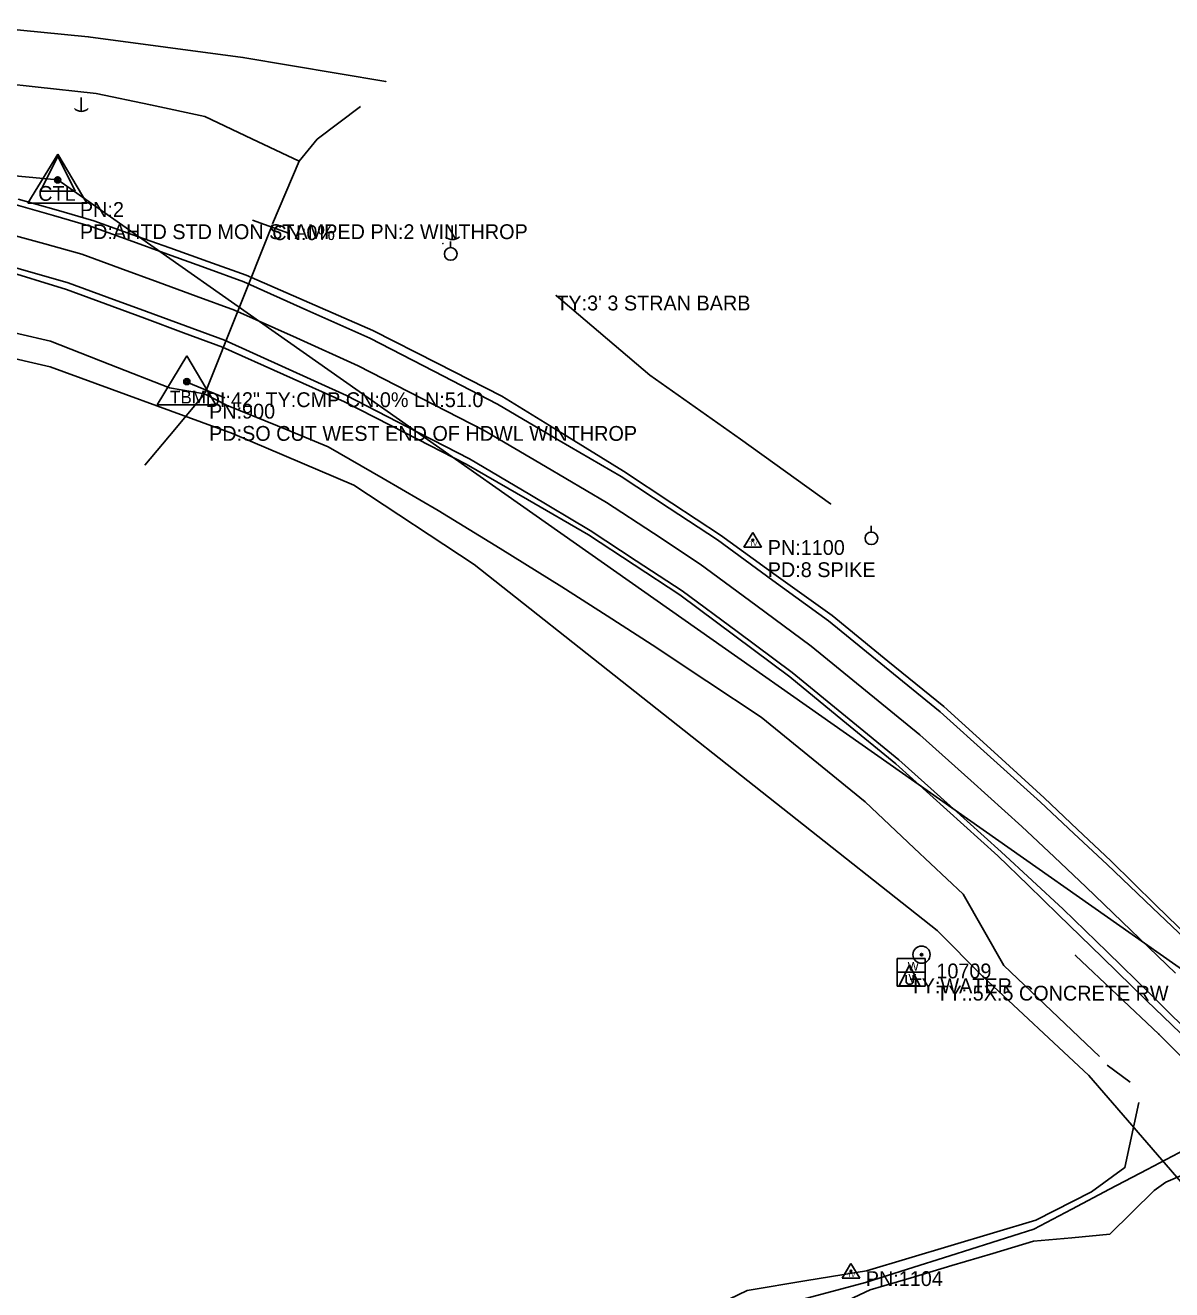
# Model space of a CAD drawing. Extents: x 592653 to 596268, y 1744647 to 1746025.
# Drawn here: x 593745.6 to 594132.6, y 1745515.6 to 1745942.5 of the extents above; entities that cross this region are included whole.
import ezdxf

# ---------------------------------------------------------------- set-up
doc = ezdxf.new("R2010")
doc.units = 0
for name, color, linetype in [('Default', 7, 'Continuous'), ('S_CAL_CORNER', 7, 'Continuous'), ('S_CROSS_DRAIN', 7, 'Continuous'), ('S_CROSS_DRAIN_ANNOT', 7, 'Continuous'), ('S_DITCHLINE', 7, 'Continuous'), ('S_DRG_PT_SYM', 7, 'Continuous'), ('S_EDGE_PAVEMENT', 7, 'Continuous'), ('S_FENCE', 7, 'Continuous'), ('S_FENCE_ANNOT', 7, 'Continuous'), ('S_GUARDRAIL', 7, 'Continuous'), ('S_HEADWALL', 7, 'Continuous'), ('S_IRON_PIN', 7, 'Continuous'), ('S_IRON_PIN_ANNOT', 7, 'Continuous'), ('S_MSC_PT_SYM', 7, 'Continuous'), ('S_PAVEMENT_CROWN', 7, 'Continuous'), ('S_PRIMARY_CTL', 7, 'Continuous'), ('S_PRIMARY_CTL_ANNOT', 7, 'Continuous'), ('S_RDW_PT_SYM', 7, 'Continuous'), ('S_SECONDARY_CTL', 7, 'Continuous'), ('S_SECONDARY_CTL_ANNOT', 7, 'Continuous'), ('S_SHOULDER', 7, 'Continuous'), ('S_STREAM', 7, 'Continuous'), ('S_UTILITY_POLE', 7, 'Continuous'), ('S_UTILITY_POLE_ANNOT', 7, 'Continuous'), ('S_UTL_PT_SYM', 7, 'Continuous'), ('S_WATER_UTILITIES', 7, 'Continuous')]:
    doc.layers.add(name, color=color, linetype=linetype)

msp = doc.modelspace()

# ---------------------------------------------------------------- linework, layer by layer
at = {"layer": 'Default'}
for p, q in [((593273.37, 1745935.37), (593756.49, 1745890.31)), ((593756.49, 1745890.31), (594217.16, 1745566.75))]:
    msp.add_line(p, q, dxfattribs=at)
at = {"layer": 'S_CAL_CORNER'}
for p, q in [((593756.58, 1745898.29), (593750.7, 1745886.47)), ((593756.58, 1745898.29), (593762.39, 1745886.47)), ((593750.7, 1745886.47), (593762.39, 1745886.47))]:
    msp.add_line(p, q, dxfattribs=at)
at = {"layer": 'S_CROSS_DRAIN'}
msp.add_line((593806.42, 1745818.59), (593828.93, 1745874.97), dxfattribs=at)
at = {"layer": 'S_DITCHLINE'}
for points in [[(593728.26, 1745923.93), (593748.84, 1745921.72), (593769.43, 1745919.51), (593787.8, 1745915.6), (593806.18, 1745911.7), (593822.07, 1745904.18), (593837.96, 1745896.66), (593844.05, 1745904.03), (593858.74, 1745915.04)], [(593829, 1745875.46), (593837.96, 1745896.66)], [(593732.61, 1745840.86), (593754.04, 1745835.83), (593774.14, 1745827.94), (593794.25, 1745820.05), (593806.09, 1745818.04), (593813.44, 1745814.3), (593830.65, 1745807.24), (593847.85, 1745800.18), (593866.41, 1745789.44), (593884.96, 1745778.71), (593905.82, 1745765.81), (593926.68, 1745752.91), (593941.94, 1745743.1), (593957.2, 1745733.29), (593975.6, 1745721.11), (593994, 1745708.92), (594011.55, 1745694.61), (594029.1, 1745680.29), (594045.62, 1745664.7), (594062.14, 1745649.11), (594069.01, 1745637.11), (594075.89, 1745625.1), (594092.04, 1745609.72), (594108.19, 1745594.34)], [(593806.09, 1745818.04), (593796.01, 1745806.03), (593785.93, 1745794.02)], [(594110.76, 1745591.41), (594118.5, 1745585.73)]]:
    msp.add_lwpolyline(points, dxfattribs=at)
at = {"layer": 'S_DRG_PT_SYM'}
for points in [[(593828.93, 1745874.97), (593828.93, 1745875.02), (593828.93, 1745874.97), (593828.88, 1745874.97), (593828.93, 1745874.97), (593828.93, 1745874.92), (593828.93, 1745874.97), (593828.98, 1745874.97)], [(593806.42, 1745818.59), (593806.42, 1745818.64), (593806.42, 1745818.59), (593806.37, 1745818.59), (593806.42, 1745818.59), (593806.42, 1745818.54), (593806.42, 1745818.59), (593806.47, 1745818.59)]]:
    msp.add_lwpolyline(points, dxfattribs=at)
at = {"layer": 'S_EDGE_PAVEMENT'}
for points in [[(593742.48, 1745881.85), (593755.13, 1745878.23), (593767.77, 1745874.61), (593780.64, 1745869.94), (593793.52, 1745865.26), (593806.4, 1745860.59), (593819.28, 1745855.91), (593840.58, 1745846.36), (593861.88, 1745836.81), (593883.43, 1745825.68), (593904.98, 1745814.55), (593925.83, 1745802.37), (593946.68, 1745790.19), (593962.93, 1745779.46), (593979.18, 1745768.73), (593997.95, 1745755.07), (594016.72, 1745741.41), (594035.56, 1745726.07), (594054.39, 1745710.73), (594071.35, 1745695.45), (594088.31, 1745680.17), (594099.54, 1745669.66), (594110.78, 1745659.14), (594126.08, 1745644.58), (594141.37, 1745630.02)], [(593736.79, 1745862.21), (593760.04, 1745855.57), (593773.24, 1745850.73), (593786.45, 1745845.88), (593799.65, 1745841.04), (593812.85, 1745836.19), (593833.41, 1745826.86), (593853.98, 1745817.53), (593874.73, 1745806.84), (593895.48, 1745796.15), (593915.85, 1745784.04), (593936.23, 1745771.93), (593951.75, 1745761.74), (593967.28, 1745751.55), (593985.88, 1745737.79), (594004.47, 1745724.03), (594022.45, 1745709.24), (594040.43, 1745694.46), (594057.74, 1745678.93), (594075.05, 1745663.41), (594085.5, 1745653.77), (594095.94, 1745644.13), (594110.75, 1745629.73), (594125.57, 1745615.32), (594142.37, 1745598.49)]]:
    msp.add_lwpolyline(points, dxfattribs=at)
at = {"layer": 'S_FENCE'}
for p, q in [((593726.74, 1745942.49), (593766.83, 1745938.65)), ((593766.83, 1745938.65), (593819.01, 1745931.67)), ((593819.01, 1745931.67), (593867.23, 1745923.48)), ((593924.81, 1745851.23), (593956.44, 1745824.35)), ((593697.66, 1745840.19), (593753.98, 1745827.15)), ((593753.98, 1745827.15), (593815.53, 1745804.73)), ((593956.44, 1745824.35), (593986.99, 1745802.74)), ((593815.53, 1745804.73), (593856.45, 1745787.24)), ((593986.99, 1745802.74), (594017.4, 1745780.93)), ((593856.45, 1745787.24), (593897.05, 1745760.44)), ((593897.05, 1745760.44), (594053.41, 1745636.94)), ((594053.41, 1745636.94), (594068.9, 1745621.22)), ((594068.9, 1745621.22), (594104.6, 1745587.97)), ((594104.6, 1745587.97), (594151.71, 1745533.43))]:
    msp.add_line(p, q, dxfattribs=at)
at = {"layer": 'S_GUARDRAIL'}
for p, q in [((594128.25, 1745601.85), (594100.13, 1745628.47)), ((594159.03, 1745570.98), (594128.25, 1745601.85))]:
    msp.add_line(p, q, dxfattribs=at)
at = {"layer": 'S_HEADWALL'}
for points in [[(593822.26, 1745876.72), (593834.42, 1745872.32)], [(593800.05, 1745821.96), (593812.87, 1745816.71)]]:
    msp.add_lwpolyline(points, dxfattribs=at)
at = {"layer": 'S_IRON_PIN'}
for radius in [2.91, 0.411, 0.262, 0.212, 0.145, 0.0822, 0.0581]:
    msp.add_circle((594048.12, 1745628.74), radius, dxfattribs=at)
at = {"layer": 'S_MSC_PT_SYM'}
for points in [[(593766.83, 1745938.65), (593766.83, 1745938.7), (593766.83, 1745938.65), (593766.78, 1745938.65), (593766.83, 1745938.65), (593766.83, 1745938.6), (593766.83, 1745938.65), (593766.88, 1745938.65)], [(593819.01, 1745931.67), (593819.01, 1745931.72), (593819.01, 1745931.67), (593818.96, 1745931.67), (593819.01, 1745931.67), (593819.01, 1745931.62), (593819.01, 1745931.67), (593819.06, 1745931.67)], [(593867.23, 1745923.48), (593867.23, 1745923.53), (593867.23, 1745923.48), (593867.18, 1745923.48), (593867.23, 1745923.48), (593867.23, 1745923.43), (593867.23, 1745923.48), (593867.28, 1745923.48)], [(593924.81, 1745851.23), (593924.81, 1745851.28), (593924.81, 1745851.23), (593924.76, 1745851.23), (593924.81, 1745851.23), (593924.81, 1745851.18), (593924.81, 1745851.23), (593924.86, 1745851.23)], [(593753.98, 1745827.15), (593753.98, 1745827.2), (593753.98, 1745827.15), (593753.93, 1745827.15), (593753.98, 1745827.15), (593753.98, 1745827.1), (593753.98, 1745827.15), (593754.03, 1745827.15)], [(593956.44, 1745824.35), (593956.44, 1745824.4), (593956.44, 1745824.35), (593956.39, 1745824.35), (593956.44, 1745824.35), (593956.44, 1745824.3), (593956.44, 1745824.35), (593956.49, 1745824.35)], [(593815.53, 1745804.73), (593815.53, 1745804.78), (593815.53, 1745804.73), (593815.48, 1745804.73), (593815.53, 1745804.73), (593815.53, 1745804.68), (593815.53, 1745804.73), (593815.58, 1745804.73)], [(593986.99, 1745802.74), (593986.99, 1745802.79), (593986.99, 1745802.74), (593986.94, 1745802.74), (593986.99, 1745802.74), (593986.99, 1745802.69), (593986.99, 1745802.74), (593987.04, 1745802.74)], [(593856.45, 1745787.24), (593856.45, 1745787.29), (593856.45, 1745787.24), (593856.4, 1745787.24), (593856.45, 1745787.24), (593856.45, 1745787.19), (593856.45, 1745787.24), (593856.5, 1745787.24)], [(594017.4, 1745780.93), (594017.4, 1745780.98), (594017.4, 1745780.93), (594017.35, 1745780.93), (594017.4, 1745780.93), (594017.4, 1745780.88), (594017.4, 1745780.93), (594017.45, 1745780.93)], [(593897.05, 1745760.44), (593897.05, 1745760.49), (593897.05, 1745760.44), (593897, 1745760.44), (593897.05, 1745760.44), (593897.05, 1745760.39), (593897.05, 1745760.44), (593897.1, 1745760.44)], [(594053.41, 1745636.94), (594053.41, 1745636.99), (594053.41, 1745636.94), (594053.36, 1745636.94), (594053.41, 1745636.94), (594053.41, 1745636.89), (594053.41, 1745636.94), (594053.46, 1745636.94)], [(594068.9, 1745621.22), (594068.9, 1745621.27), (594068.9, 1745621.22), (594068.85, 1745621.22), (594068.9, 1745621.22), (594068.9, 1745621.17), (594068.9, 1745621.22), (594068.95, 1745621.22)], [(594104.6, 1745587.97), (594104.6, 1745588.02), (594104.6, 1745587.97), (594104.55, 1745587.97), (594104.6, 1745587.97), (594104.6, 1745587.92), (594104.6, 1745587.97), (594104.65, 1745587.97)]]:
    msp.add_lwpolyline(points, dxfattribs=at)
at = {"layer": 'S_PAVEMENT_CROWN'}
msp.add_lwpolyline([(593739.78, 1745872.08), (593752.2, 1745868.67), (593764.61, 1745865.25), (593777.5, 1745860.53), (593790.38, 1745855.81), (593803.26, 1745851.08), (593816.15, 1745846.36), (593837.06, 1745836.96), (593857.97, 1745827.57), (593879.21, 1745816.61), (593900.45, 1745805.66), (593921.13, 1745793.52), (593941.81, 1745781.37), (593957.61, 1745770.98), (593973.42, 1745760.59), (593992.13, 1745746.72), (594010.84, 1745732.86), (594029.2, 1745717.91), (594047.56, 1745702.96), (594064.77, 1745687.48), (594081.97, 1745671.99), (594092.84, 1745661.77), (594103.7, 1745651.56), (594118.8, 1745637.01), (594133.89, 1745622.47)], dxfattribs=at)
at = {"layer": 'S_PRIMARY_CTL'}
for p, q in [((593756.49, 1745899.01), (593746.45, 1745882.49)), ((593756.49, 1745899.01), (593746.45, 1745882.49)), ((593756.49, 1745899.01), (593766.31, 1745882.49)), ((593756.49, 1745899.01), (593766.31, 1745882.49)), ((593746.45, 1745882.49), (593766.31, 1745882.49)), ((593746.45, 1745882.49), (593766.31, 1745882.49)), ((593800.09, 1745830.91), (593790.05, 1745814.4)), ((593800.09, 1745830.91), (593790.05, 1745814.4)), ((593800.09, 1745830.91), (593809.91, 1745814.4)), ((593800.09, 1745830.91), (593809.91, 1745814.4)), ((593790.05, 1745814.4), (593809.91, 1745814.4)), ((593790.05, 1745814.4), (593809.91, 1745814.4))]:
    msp.add_line(p, q, dxfattribs=at)
for centre, radius in [((593756.49, 1745890.31), 1.04), ((593756.49, 1745890.31), 1.04), ((593756.49, 1745890.31), 0.609), ((593756.49, 1745890.31), 0.609), ((593756.49, 1745890.31), 0.344), ((593756.49, 1745890.31), 0.344), ((593800.09, 1745822.21), 1.04), ((593800.09, 1745822.21), 1.04), ((593800.09, 1745822.21), 0.609), ((593800.09, 1745822.21), 0.609), ((593800.09, 1745822.21), 0.344), ((593800.09, 1745822.21), 0.344)]:
    msp.add_circle(centre, radius, dxfattribs=at)
at = {"layer": 'S_RDW_PT_SYM'}
for points in [[(594100.13, 1745628.47), (594100.13, 1745628.52), (594100.13, 1745628.47), (594100.08, 1745628.47), (594100.13, 1745628.47), (594100.13, 1745628.42), (594100.13, 1745628.47), (594100.18, 1745628.47)], [(594128.25, 1745601.85), (594128.25, 1745601.9), (594128.25, 1745601.85), (594128.2, 1745601.85), (594128.25, 1745601.85), (594128.25, 1745601.8), (594128.25, 1745601.85), (594128.3, 1745601.85)]]:
    msp.add_lwpolyline(points, dxfattribs=at)
at = {"layer": 'S_SECONDARY_CTL'}
for p, q in [((593991.19, 1745771.31), (593988.18, 1745766.36)), ((593991.19, 1745771.31), (593994.14, 1745766.36)), ((593988.18, 1745766.36), (593994.14, 1745766.36)), ((594024.28, 1745524.48), (594021.27, 1745519.52)), ((594024.28, 1745524.48), (594027.23, 1745519.52)), ((594021.27, 1745519.52), (594027.23, 1745519.52))]:
    msp.add_line(p, q, dxfattribs=at)
for centre, radius in [((593991.19, 1745768.7), 0.311), ((593991.19, 1745768.7), 0.183), ((593991.19, 1745768.7), 0.103), ((594024.28, 1745521.87), 0.311), ((594024.28, 1745521.87), 0.183), ((594024.28, 1745521.87), 0.103)]:
    msp.add_circle(centre, radius, dxfattribs=at)
at = {"layer": 'S_SHOULDER'}
for points in [[(593743.17, 1745883.79), (593755.94, 1745880.14), (593768.72, 1745876.49), (593781.56, 1745871.91), (593794.39, 1745867.32), (593807.23, 1745862.73), (593820.07, 1745858.15), (593841.47, 1745848.81), (593862.86, 1745839.46), (593884.63, 1745828.38), (593906.4, 1745817.29), (593926.93, 1745804.63), (593947.46, 1745791.96), (593963.85, 1745781.17), (593980.24, 1745770.37), (593999.09, 1745756.79), (594017.94, 1745743.21), (594036.79, 1745727.86), (594055.65, 1745712.51), (594072.6, 1745697.1), (594089.55, 1745681.68), (594100.79, 1745671.02), (594112.03, 1745660.36), (594127.14, 1745645.61), (594142.26, 1745630.86)], [(593736.68, 1745860.22), (593759.5, 1745853.33), (593772.65, 1745848.46), (593785.8, 1745843.59), (593798.96, 1745838.71), (593812.11, 1745833.84), (593832.71, 1745824.58), (593853.31, 1745815.33), (593873.85, 1745804.85), (593894.39, 1745794.37), (593915.04, 1745782.43), (593935.69, 1745770.49), (593951.08, 1745760.36), (593966.48, 1745750.23), (593985.09, 1745736.37), (594003.69, 1745722.51), (594021.57, 1745707.83), (594039.44, 1745693.16), (594056.68, 1745677.62), (594073.91, 1745662.08), (594084.08, 1745652.19), (594094.26, 1745642.29), (594109.18, 1745627.8), (594124.11, 1745613.31), (594141.15, 1745596.88)]]:
    msp.add_lwpolyline(points, dxfattribs=at)
at = {"layer": 'S_STREAM'}
for points in [[(594121.51, 1745578.81), (594116.8, 1745556.87), (594105.51, 1745548.63), (594086.68, 1745539.13), (594072.4, 1745534.84), (594058.11, 1745530.56), (594043.83, 1745526.27), (594029.55, 1745521.98), (594009.42, 1745518.69), (593989.29, 1745515.39), (593977.35, 1745509.59), (593965.4, 1745503.78), (593953.45, 1745497.98), (593941.51, 1745492.18), (593927.89, 1745487.08), (593914.27, 1745481.98), (593900.72, 1745470.7), (593887.18, 1745459.42), (593873.64, 1745448.14), (593860.09, 1745436.87)], [(594137.06, 1745562.92), (594124.31, 1745556.22), (594111.56, 1745549.51), (594098.82, 1745542.81), (594086.07, 1745536.1), (594071.86, 1745531.58), (594057.65, 1745527.06), (594043.43, 1745522.54), (594029.22, 1745518.02), (594011.13, 1745513.25), (593993.03, 1745508.47), (593980.89, 1745502.69), (593968.75, 1745496.9), (593956.6, 1745491.11), (593944.46, 1745485.33), (593933.64, 1745477.75), (593922.83, 1745470.16), (593907.77, 1745458.25), (593892.71, 1745446.34), (593877.66, 1745434.43), (593862.6, 1745422.52)], [(594146.88, 1745558.89), (594130.58, 1745551.98), (594126.65, 1745549.15), (594111.68, 1745534.37), (594098.81, 1745533.18), (594085.94, 1745531.99), (594072.15, 1745527.89), (594058.36, 1745523.78), (594044.57, 1745519.68), (594030.78, 1745515.57), (594012.34, 1745506.91), (593993.89, 1745498.25), (593982.01, 1745493.42), (593970.13, 1745488.59), (593958.26, 1745483.76), (593946.38, 1745478.93), (593928.65, 1745464.69), (593914.46, 1745451.61), (593900.27, 1745438.53), (593886.09, 1745425.45), (593871.9, 1745412.37)]]:
    msp.add_lwpolyline(points, dxfattribs=at)
at = {"layer": 'S_UTILITY_POLE'}
for p, q in [((593764.4, 1745918.16), (593764.4, 1745913.43)), ((593889.69, 1745874.86), (593889.69, 1745870.13)), ((593889.05, 1745867.45), (593889.05, 1745869.55)), ((594031.08, 1745771.43), (594031.08, 1745773.54)), ((594044.09, 1745625.27), (594040.56, 1745618.18)), ((594044.09, 1745625.27), (594047.58, 1745618.18)), ((594040.56, 1745618.18), (594047.58, 1745618.18)), ((594042.89, 1745619.42), (594042.89, 1745621.86)), ((594043.51, 1745618.76), (594042.89, 1745619.42)), ((594044.71, 1745618.76), (594043.51, 1745618.76)), ((594045.25, 1745619.42), (594044.71, 1745618.76)), ((594045.25, 1745621.86), (594045.25, 1745619.42))]:
    msp.add_line(p, q, dxfattribs=at)
for centre in [(593889.17, 1745865.3), (594031.2, 1745769.29)]:
    msp.add_circle(centre, 2.13, dxfattribs=at)
for centre in [(593764.47, 1745916.85), (593889.75, 1745873.56)]:
    msp.add_arc(centre, 3.41, 226.3972, 313.6028, dxfattribs=at)
at = {"layer": 'S_UTL_PT_SYM'}
msp.add_lwpolyline([(593886.54, 1745868.79), (593886.54, 1745868.84), (593886.54, 1745868.79), (593886.49, 1745868.79), (593886.54, 1745868.79), (593886.54, 1745868.74), (593886.54, 1745868.79), (593886.59, 1745868.79)], dxfattribs=at)
at = {"layer": 'S_WATER_UTILITIES'}
for p, q in [((594039.88, 1745627.46), (594049.29, 1745627.46)), ((594039.88, 1745618.05), (594039.88, 1745627.46)), ((594049.29, 1745627.46), (594049.29, 1745618.05)), ((594039.88, 1745622.77), (594049.29, 1745622.77)), ((594049.29, 1745618.05), (594039.88, 1745618.05))]:
    msp.add_line(p, q, dxfattribs=at)

# ---------------------------------------------------------------- texts
at = {"layer": 'S_CROSS_DRAIN_ANNOT'}
for s, p in [('CN:0%', (593828.93, 1745869.97)), ('DI:42" TY:CMP CN:0% LN:51.0', (593806.42, 1745813.59))]:
    msp.add_text(s, height=5, dxfattribs=at).set_placement(p)
at = {"layer": 'S_FENCE_ANNOT'}
msp.add_text("TY:3' 3 STRAN BARB", height=5, dxfattribs=at).set_placement((593924.81, 1745846.23))
at = {"layer": 'S_IRON_PIN_ANNOT'}
for s, p in [('10709', (594053.12, 1745620.74)), ('TY:.5X.5 CONCRETE RW', (594053.12, 1745613.24))]:
    msp.add_text(s, height=5, dxfattribs=at).set_placement(p)
at = {"layer": 'S_PRIMARY_CTL'}
for s, height, p in [('CTL', 5, (593749.9, 1745883.23)), ('CTL', 5, (593749.9, 1745883.23)), ('TBM', 4.287, (593794.43, 1745814.82)), ('TBM', 4.287, (593794.43, 1745814.82))]:
    msp.add_text(s, height=height, rotation=360, dxfattribs=at).set_placement(p)
at = {"layer": 'S_PRIMARY_CTL_ANNOT'}
for s, p in [('PN:2', (593763.99, 1745877.81)), ('PD:AHTD STD MON STAMPED PN:2 WINTHROP', (593763.99, 1745870.31)), ('PN:900', (593807.59, 1745809.71)), ('PD:SO CUT WEST END OF HDWL WINTHROP', (593807.59, 1745802.21))]:
    msp.add_text(s, height=5, dxfattribs=at).set_placement(p)
at = {"layer": 'S_SECONDARY_CTL'}
for p in [(593989.99, 1745766.69), (594023.08, 1745519.86)]:
    msp.add_text('TV', height=1.5, rotation=360, dxfattribs=at).set_placement(p)
at = {"layer": 'S_SECONDARY_CTL_ANNOT'}
for s, p in [('PN:1100', (593996.19, 1745763.7)), ('PD:8 SPIKE', (593996.19, 1745756.2)), ('PN:1104', (594029.28, 1745516.87))]:
    msp.add_text(s, height=5, dxfattribs=at).set_placement(p)
at = {"layer": 'S_UTILITY_POLE_ANNOT'}
msp.add_text('TY:WATER', height=5, dxfattribs=at).set_placement((594044.09, 1745615.73))
at = {"layer": 'S_WATER_UTILITIES'}
for s, p in [('W', (594043.43, 1745623.3)), ('V', (594043.66, 1745619.24))]:
    msp.add_text(s, height=3, rotation=360, dxfattribs=at).set_placement(p)

doc.saveas('drawing.dxf')
